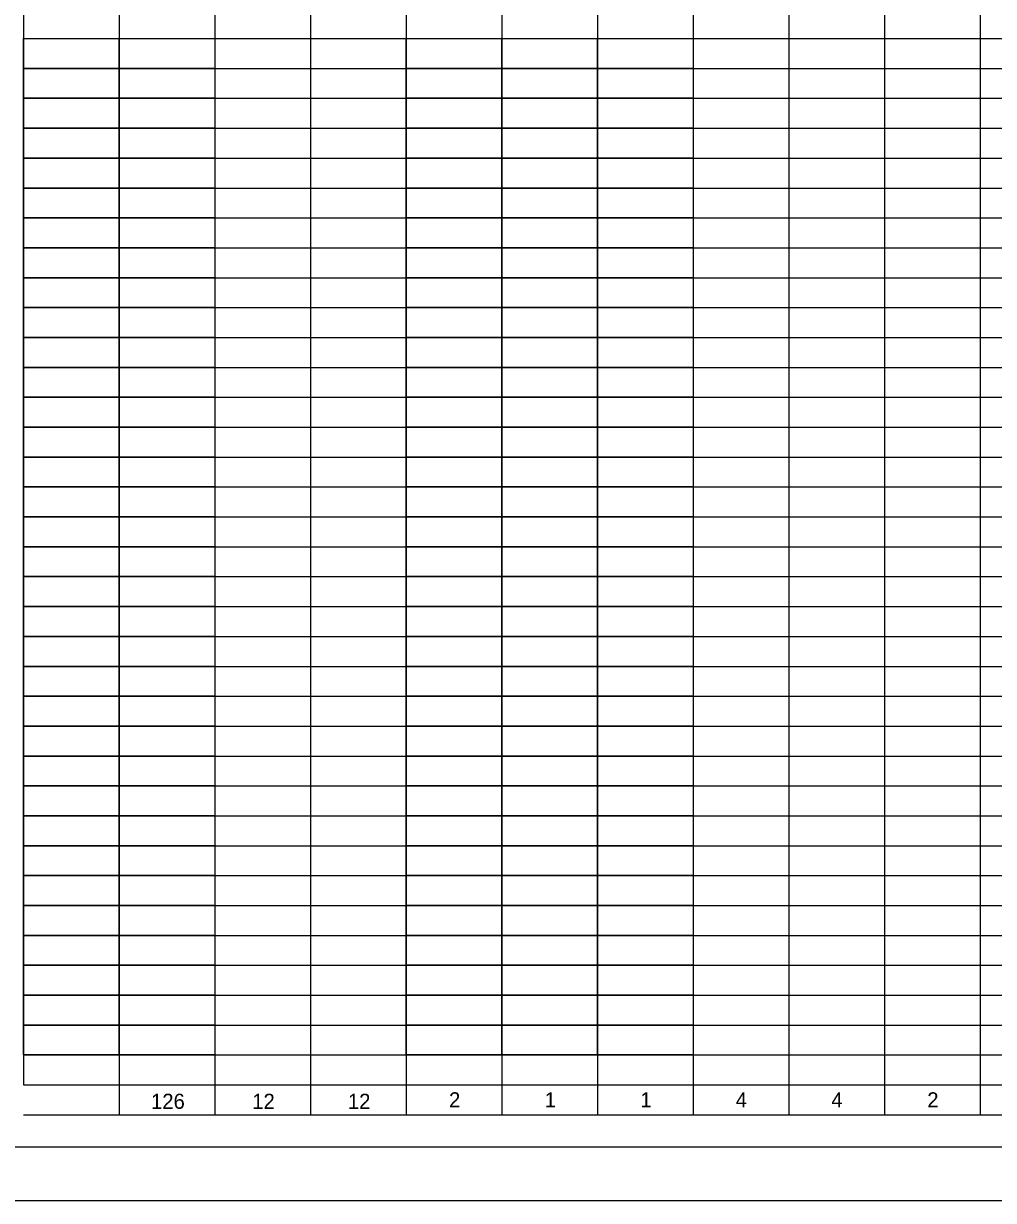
# Model space of a CAD drawing. Extents: x 0 to 34, y 0 to 22.
# Drawn here: x 7.83 to 16.91, y 0 to 11.01 of the extents above; entities that cross this region are included whole.
import ezdxf

# ---------------------------------------------------------------- set-up
doc = ezdxf.new("R2010")
doc.units = 0
for name, color, linetype in [('Default', 7, 'Continuous'), ('SH_Border', 7, 'Continuous'), ('SH_Cut_Line', 7, 'Continuous')]:
    doc.layers.add(name, color=color, linetype=linetype)

msp = doc.modelspace()

# ---------------------------------------------------------------- linework, layer by layer
at = {"layer": 'Default'}
for p, q in [((7.833, 21.5), (7.833, 1.081)), ((8.728, 21.5), (8.728, 0.801)), ((14.098, 21.5), (14.098, 0.801)), ((9.623, 21.22), (9.623, 0.801)), ((10.518, 21.22), (10.518, 0.801)), ((11.413, 21.22), (11.413, 0.801)), ((12.308, 21.22), (12.308, 0.801)), ((13.203, 21.22), (13.203, 0.801)), ((14.993, 21.22), (14.993, 0.801)), ((15.888, 21.22), (15.888, 0.801)), ((16.784, 21.22), (16.784, 0.801)), ((7.833, 10.871), (21.259, 10.871)), ((7.833, 10.591), (21.259, 10.591)), ((7.833, 10.311), (21.259, 10.311)), ((7.833, 10.032), (21.259, 10.032)), ((7.833, 9.752), (21.259, 9.752)), ((7.833, 9.472), (21.259, 9.472)), ((7.833, 9.193), (21.259, 9.193)), ((7.833, 8.913), (21.259, 8.913)), ((7.833, 8.633), (21.259, 8.633)), ((7.833, 8.353), (21.259, 8.353)), ((7.833, 8.074), (21.259, 8.074)), ((7.833, 7.794), (21.259, 7.794)), ((7.833, 7.514), (21.259, 7.514)), ((7.833, 7.235), (21.259, 7.235)), ((7.833, 6.955), (21.259, 6.955)), ((7.833, 6.675), (21.259, 6.675)), ((7.833, 6.395), (21.259, 6.395)), ((7.833, 6.116), (21.259, 6.116)), ((7.833, 5.836), (21.259, 5.836)), ((7.833, 5.556), (21.259, 5.556)), ((7.833, 5.277), (21.259, 5.277)), ((7.833, 4.997), (21.259, 4.997)), ((7.833, 4.717), (21.259, 4.717)), ((7.833, 4.437), (21.259, 4.437)), ((7.833, 4.158), (21.259, 4.158)), ((7.833, 3.878), (21.259, 3.878)), ((7.833, 3.598), (21.259, 3.598)), ((7.833, 3.319), (21.259, 3.319)), ((7.833, 3.039), (21.259, 3.039)), ((7.833, 2.759), (21.259, 2.759)), ((7.833, 2.479), (21.259, 2.479)), ((7.833, 2.2), (21.259, 2.2)), ((7.833, 1.92), (21.259, 1.92)), ((7.833, 1.64), (21.259, 1.64)), ((7.833, 1.361), (21.259, 1.361)), ((7.833, 1.081), (21.259, 1.081)), ((7.833, 0.801), (21.259, 0.801))]:
    msp.add_line(p, q, dxfattribs=at)
for points in [[(7.833, 10.871), (8.728, 10.871), (8.728, 10.591), (7.833, 10.591)], [(8.728, 10.871), (9.623, 10.871), (9.623, 10.591), (8.728, 10.591)], [(11.413, 10.871), (12.308, 10.871), (12.308, 10.591), (11.413, 10.591)], [(12.308, 10.871), (13.203, 10.871), (13.203, 10.591), (12.308, 10.591)], [(13.203, 10.871), (14.098, 10.871), (14.098, 10.591), (13.203, 10.591)], [(7.833, 10.591), (8.728, 10.591), (8.728, 10.311), (7.833, 10.311)], [(8.728, 10.591), (9.623, 10.591), (9.623, 10.311), (8.728, 10.311)], [(11.413, 10.591), (12.308, 10.591), (12.308, 10.311), (11.413, 10.311)], [(12.308, 10.591), (13.203, 10.591), (13.203, 10.311), (12.308, 10.311)], [(13.203, 10.591), (14.098, 10.591), (14.098, 10.311), (13.203, 10.311)], [(7.833, 10.311), (8.728, 10.311), (8.728, 10.032), (7.833, 10.032)], [(8.728, 10.311), (9.623, 10.311), (9.623, 10.032), (8.728, 10.032)], [(11.413, 10.311), (12.308, 10.311), (12.308, 10.032), (11.413, 10.032)], [(12.308, 10.311), (13.203, 10.311), (13.203, 10.032), (12.308, 10.032)], [(13.203, 10.311), (14.098, 10.311), (14.098, 10.032), (13.203, 10.032)], [(7.833, 10.032), (8.728, 10.032), (8.728, 9.752), (7.833, 9.752)], [(8.728, 10.032), (9.623, 10.032), (9.623, 9.752), (8.728, 9.752)], [(11.413, 10.032), (12.308, 10.032), (12.308, 9.752), (11.413, 9.752)], [(12.308, 10.032), (13.203, 10.032), (13.203, 9.752), (12.308, 9.752)], [(13.203, 10.032), (14.098, 10.032), (14.098, 9.752), (13.203, 9.752)], [(7.833, 9.752), (8.728, 9.752), (8.728, 9.472), (7.833, 9.472)], [(8.728, 9.752), (9.623, 9.752), (9.623, 9.472), (8.728, 9.472)], [(11.413, 9.752), (12.308, 9.752), (12.308, 9.472), (11.413, 9.472)], [(12.308, 9.752), (13.203, 9.752), (13.203, 9.472), (12.308, 9.472)], [(13.203, 9.752), (14.098, 9.752), (14.098, 9.472), (13.203, 9.472)], [(7.833, 9.472), (8.728, 9.472), (8.728, 9.193), (7.833, 9.193)], [(8.728, 9.472), (9.623, 9.472), (9.623, 9.193), (8.728, 9.193)], [(11.413, 9.472), (12.308, 9.472), (12.308, 9.193), (11.413, 9.193)], [(12.308, 9.472), (13.203, 9.472), (13.203, 9.193), (12.308, 9.193)], [(13.203, 9.472), (14.098, 9.472), (14.098, 9.193), (13.203, 9.193)], [(7.833, 9.193), (8.728, 9.193), (8.728, 8.913), (7.833, 8.913)], [(8.728, 9.193), (9.623, 9.193), (9.623, 8.913), (8.728, 8.913)], [(11.413, 9.193), (12.308, 9.193), (12.308, 8.913), (11.413, 8.913)], [(12.308, 9.193), (13.203, 9.193), (13.203, 8.913), (12.308, 8.913)], [(13.203, 9.193), (14.098, 9.193), (14.098, 8.913), (13.203, 8.913)], [(7.833, 8.913), (8.728, 8.913), (8.728, 8.633), (7.833, 8.633)], [(8.728, 8.913), (9.623, 8.913), (9.623, 8.633), (8.728, 8.633)], [(11.413, 8.913), (12.308, 8.913), (12.308, 8.633), (11.413, 8.633)], [(12.308, 8.913), (13.203, 8.913), (13.203, 8.633), (12.308, 8.633)], [(13.203, 8.913), (14.098, 8.913), (14.098, 8.633), (13.203, 8.633)], [(7.833, 8.633), (8.728, 8.633), (8.728, 8.353), (7.833, 8.353)], [(8.728, 8.633), (9.623, 8.633), (9.623, 8.353), (8.728, 8.353)], [(11.413, 8.633), (12.308, 8.633), (12.308, 8.353), (11.413, 8.353)], [(12.308, 8.633), (13.203, 8.633), (13.203, 8.353), (12.308, 8.353)], [(13.203, 8.633), (14.098, 8.633), (14.098, 8.353), (13.203, 8.353)], [(7.833, 8.353), (8.728, 8.353), (8.728, 8.074), (7.833, 8.074)], [(8.728, 8.353), (9.623, 8.353), (9.623, 8.074), (8.728, 8.074)], [(11.413, 8.353), (12.308, 8.353), (12.308, 8.074), (11.413, 8.074)], [(12.308, 8.353), (13.203, 8.353), (13.203, 8.074), (12.308, 8.074)], [(13.203, 8.353), (14.098, 8.353), (14.098, 8.074), (13.203, 8.074)], [(7.833, 8.074), (8.728, 8.074), (8.728, 7.794), (7.833, 7.794)], [(8.728, 8.074), (9.623, 8.074), (9.623, 7.794), (8.728, 7.794)], [(11.413, 8.074), (12.308, 8.074), (12.308, 7.794), (11.413, 7.794)], [(12.308, 8.074), (13.203, 8.074), (13.203, 7.794), (12.308, 7.794)], [(13.203, 8.074), (14.098, 8.074), (14.098, 7.794), (13.203, 7.794)], [(7.833, 7.794), (8.728, 7.794), (8.728, 7.514), (7.833, 7.514)], [(8.728, 7.794), (9.623, 7.794), (9.623, 7.514), (8.728, 7.514)], [(11.413, 7.794), (12.308, 7.794), (12.308, 7.514), (11.413, 7.514)], [(12.308, 7.794), (13.203, 7.794), (13.203, 7.514), (12.308, 7.514)], [(13.203, 7.794), (14.098, 7.794), (14.098, 7.514), (13.203, 7.514)], [(7.833, 7.514), (8.728, 7.514), (8.728, 7.235), (7.833, 7.235)], [(8.728, 7.514), (9.623, 7.514), (9.623, 7.235), (8.728, 7.235)], [(11.413, 7.514), (12.308, 7.514), (12.308, 7.235), (11.413, 7.235)], [(12.308, 7.514), (13.203, 7.514), (13.203, 7.235), (12.308, 7.235)], [(13.203, 7.514), (14.098, 7.514), (14.098, 7.235), (13.203, 7.235)], [(7.833, 7.235), (8.728, 7.235), (8.728, 6.955), (7.833, 6.955)], [(8.728, 7.235), (9.623, 7.235), (9.623, 6.955), (8.728, 6.955)], [(11.413, 7.235), (12.308, 7.235), (12.308, 6.955), (11.413, 6.955)], [(12.308, 7.235), (13.203, 7.235), (13.203, 6.955), (12.308, 6.955)], [(13.203, 7.235), (14.098, 7.235), (14.098, 6.955), (13.203, 6.955)], [(7.833, 6.955), (8.728, 6.955), (8.728, 6.675), (7.833, 6.675)], [(8.728, 6.955), (9.623, 6.955), (9.623, 6.675), (8.728, 6.675)], [(11.413, 6.955), (12.308, 6.955), (12.308, 6.675), (11.413, 6.675)], [(12.308, 6.955), (13.203, 6.955), (13.203, 6.675), (12.308, 6.675)], [(13.203, 6.955), (14.098, 6.955), (14.098, 6.675), (13.203, 6.675)], [(7.833, 6.675), (8.728, 6.675), (8.728, 6.395), (7.833, 6.395)], [(8.728, 6.675), (9.623, 6.675), (9.623, 6.395), (8.728, 6.395)], [(11.413, 6.675), (12.308, 6.675), (12.308, 6.395), (11.413, 6.395)], [(12.308, 6.675), (13.203, 6.675), (13.203, 6.395), (12.308, 6.395)], [(13.203, 6.675), (14.098, 6.675), (14.098, 6.395), (13.203, 6.395)], [(7.833, 6.395), (8.728, 6.395), (8.728, 6.116), (7.833, 6.116)], [(8.728, 6.395), (9.623, 6.395), (9.623, 6.116), (8.728, 6.116)], [(11.413, 6.395), (12.308, 6.395), (12.308, 6.116), (11.413, 6.116)], [(12.308, 6.395), (13.203, 6.395), (13.203, 6.116), (12.308, 6.116)], [(13.203, 6.395), (14.098, 6.395), (14.098, 6.116), (13.203, 6.116)], [(7.833, 6.116), (8.728, 6.116), (8.728, 5.836), (7.833, 5.836)], [(8.728, 6.116), (9.623, 6.116), (9.623, 5.836), (8.728, 5.836)], [(11.413, 6.116), (12.308, 6.116), (12.308, 5.836), (11.413, 5.836)], [(12.308, 6.116), (13.203, 6.116), (13.203, 5.836), (12.308, 5.836)], [(13.203, 6.116), (14.098, 6.116), (14.098, 5.836), (13.203, 5.836)], [(7.833, 5.836), (8.728, 5.836), (8.728, 5.556), (7.833, 5.556)], [(8.728, 5.836), (9.623, 5.836), (9.623, 5.556), (8.728, 5.556)], [(11.413, 5.836), (12.308, 5.836), (12.308, 5.556), (11.413, 5.556)], [(12.308, 5.836), (13.203, 5.836), (13.203, 5.556), (12.308, 5.556)], [(13.203, 5.836), (14.098, 5.836), (14.098, 5.556), (13.203, 5.556)], [(7.833, 5.556), (8.728, 5.556), (8.728, 5.277), (7.833, 5.277)], [(8.728, 5.556), (9.623, 5.556), (9.623, 5.277), (8.728, 5.277)], [(11.413, 5.556), (12.308, 5.556), (12.308, 5.277), (11.413, 5.277)], [(12.308, 5.556), (13.203, 5.556), (13.203, 5.277), (12.308, 5.277)], [(13.203, 5.556), (14.098, 5.556), (14.098, 5.277), (13.203, 5.277)], [(7.833, 5.277), (8.728, 5.277), (8.728, 4.997), (7.833, 4.997)], [(8.728, 5.277), (9.623, 5.277), (9.623, 4.997), (8.728, 4.997)], [(11.413, 5.277), (12.308, 5.277), (12.308, 4.997), (11.413, 4.997)], [(12.308, 5.277), (13.203, 5.277), (13.203, 4.997), (12.308, 4.997)], [(13.203, 5.277), (14.098, 5.277), (14.098, 4.997), (13.203, 4.997)], [(7.833, 4.997), (8.728, 4.997), (8.728, 4.717), (7.833, 4.717)], [(8.728, 4.997), (9.623, 4.997), (9.623, 4.717), (8.728, 4.717)], [(11.413, 4.997), (12.308, 4.997), (12.308, 4.717), (11.413, 4.717)], [(12.308, 4.997), (13.203, 4.997), (13.203, 4.717), (12.308, 4.717)], [(13.203, 4.997), (14.098, 4.997), (14.098, 4.717), (13.203, 4.717)], [(7.833, 4.717), (8.728, 4.717), (8.728, 4.437), (7.833, 4.437)], [(8.728, 4.717), (9.623, 4.717), (9.623, 4.437), (8.728, 4.437)], [(11.413, 4.717), (12.308, 4.717), (12.308, 4.437), (11.413, 4.437)], [(12.308, 4.717), (13.203, 4.717), (13.203, 4.437), (12.308, 4.437)], [(13.203, 4.717), (14.098, 4.717), (14.098, 4.437), (13.203, 4.437)], [(7.833, 4.437), (8.728, 4.437), (8.728, 4.158), (7.833, 4.158)], [(8.728, 4.437), (9.623, 4.437), (9.623, 4.158), (8.728, 4.158)], [(11.413, 4.437), (12.308, 4.437), (12.308, 4.158), (11.413, 4.158)], [(12.308, 4.437), (13.203, 4.437), (13.203, 4.158), (12.308, 4.158)], [(13.203, 4.437), (14.098, 4.437), (14.098, 4.158), (13.203, 4.158)], [(7.833, 4.158), (8.728, 4.158), (8.728, 3.878), (7.833, 3.878)], [(8.728, 4.158), (9.623, 4.158), (9.623, 3.878), (8.728, 3.878)], [(11.413, 4.158), (12.308, 4.158), (12.308, 3.878), (11.413, 3.878)], [(12.308, 4.158), (13.203, 4.158), (13.203, 3.878), (12.308, 3.878)], [(13.203, 4.158), (14.098, 4.158), (14.098, 3.878), (13.203, 3.878)], [(7.833, 3.878), (8.728, 3.878), (8.728, 3.598), (7.833, 3.598)], [(8.728, 3.878), (9.623, 3.878), (9.623, 3.598), (8.728, 3.598)], [(11.413, 3.878), (12.308, 3.878), (12.308, 3.598), (11.413, 3.598)], [(12.308, 3.878), (13.203, 3.878), (13.203, 3.598), (12.308, 3.598)], [(13.203, 3.878), (14.098, 3.878), (14.098, 3.598), (13.203, 3.598)], [(7.833, 3.598), (8.728, 3.598), (8.728, 3.319), (7.833, 3.319)], [(8.728, 3.598), (9.623, 3.598), (9.623, 3.319), (8.728, 3.319)], [(11.413, 3.598), (12.308, 3.598), (12.308, 3.319), (11.413, 3.319)], [(12.308, 3.598), (13.203, 3.598), (13.203, 3.319), (12.308, 3.319)], [(13.203, 3.598), (14.098, 3.598), (14.098, 3.319), (13.203, 3.319)], [(7.833, 3.319), (8.728, 3.319), (8.728, 3.039), (7.833, 3.039)], [(8.728, 3.319), (9.623, 3.319), (9.623, 3.039), (8.728, 3.039)], [(11.413, 3.319), (12.308, 3.319), (12.308, 3.039), (11.413, 3.039)], [(12.308, 3.319), (13.203, 3.319), (13.203, 3.039), (12.308, 3.039)], [(13.203, 3.319), (14.098, 3.319), (14.098, 3.039), (13.203, 3.039)], [(7.833, 3.039), (8.728, 3.039), (8.728, 2.759), (7.833, 2.759)], [(8.728, 3.039), (9.623, 3.039), (9.623, 2.759), (8.728, 2.759)], [(11.413, 3.039), (12.308, 3.039), (12.308, 2.759), (11.413, 2.759)], [(12.308, 3.039), (13.203, 3.039), (13.203, 2.759), (12.308, 2.759)], [(13.203, 3.039), (14.098, 3.039), (14.098, 2.759), (13.203, 2.759)], [(7.833, 2.759), (8.728, 2.759), (8.728, 2.479), (7.833, 2.479)], [(8.728, 2.759), (9.623, 2.759), (9.623, 2.479), (8.728, 2.479)], [(11.413, 2.759), (12.308, 2.759), (12.308, 2.479), (11.413, 2.479)], [(12.308, 2.759), (13.203, 2.759), (13.203, 2.479), (12.308, 2.479)], [(13.203, 2.759), (14.098, 2.759), (14.098, 2.479), (13.203, 2.479)], [(7.833, 2.479), (8.728, 2.479), (8.728, 2.2), (7.833, 2.2)], [(8.728, 2.479), (9.623, 2.479), (9.623, 2.2), (8.728, 2.2)], [(11.413, 2.479), (12.308, 2.479), (12.308, 2.2), (11.413, 2.2)], [(12.308, 2.479), (13.203, 2.479), (13.203, 2.2), (12.308, 2.2)], [(13.203, 2.479), (14.098, 2.479), (14.098, 2.2), (13.203, 2.2)], [(7.833, 2.2), (8.728, 2.2), (8.728, 1.92), (7.833, 1.92)], [(8.728, 2.2), (9.623, 2.2), (9.623, 1.92), (8.728, 1.92)], [(11.413, 2.2), (12.308, 2.2), (12.308, 1.92), (11.413, 1.92)], [(12.308, 2.2), (13.203, 2.2), (13.203, 1.92), (12.308, 1.92)], [(13.203, 2.2), (14.098, 2.2), (14.098, 1.92), (13.203, 1.92)], [(7.833, 1.92), (8.728, 1.92), (8.728, 1.64), (7.833, 1.64)], [(8.728, 1.92), (9.623, 1.92), (9.623, 1.64), (8.728, 1.64)], [(11.413, 1.92), (12.308, 1.92), (12.308, 1.64), (11.413, 1.64)], [(12.308, 1.92), (13.203, 1.92), (13.203, 1.64), (12.308, 1.64)], [(13.203, 1.92), (14.098, 1.92), (14.098, 1.64), (13.203, 1.64)], [(7.833, 1.64), (8.728, 1.64), (8.728, 1.361), (7.833, 1.361)], [(8.728, 1.64), (9.623, 1.64), (9.623, 1.361), (8.728, 1.361)], [(11.413, 1.64), (12.308, 1.64), (12.308, 1.361), (11.413, 1.361)], [(12.308, 1.64), (13.203, 1.64), (13.203, 1.361), (12.308, 1.361)], [(13.203, 1.64), (14.098, 1.64), (14.098, 1.361), (13.203, 1.361)]]:
    msp.add_lwpolyline(points, close=True, dxfattribs=at)
at = {"layer": 'SH_Border'}
msp.add_lwpolyline([(1.5, 21.5), (33.5, 21.5), (33.5, 0.5), (1.5, 0.5)], close=True, dxfattribs=at)
at = {"layer": 'SH_Cut_Line'}
msp.add_lwpolyline([(0, 0), (34, 0), (34, 22), (0, 22)], close=True, dxfattribs=at)

# ---------------------------------------------------------------- texts
at = {"layer": 'Default'}
for s, height, p in [('126', 0.1415, (9.026, 0.857)), ('12', 0.1415, (9.973, 0.857)), ('12', 0.1415, (10.868, 0.857)), ('2', 0.142, (11.814, 0.87)), ('1', 0.142, (12.709, 0.87)), ('1', 0.142, (13.604, 0.87)), ('4', 0.142, (14.497, 0.87)), ('4', 0.142, (15.392, 0.87)), ('2', 0.142, (16.289, 0.87))]:
    msp.add_text(s, height=height, dxfattribs=at).set_placement(p)

doc.saveas('drawing.dxf')
